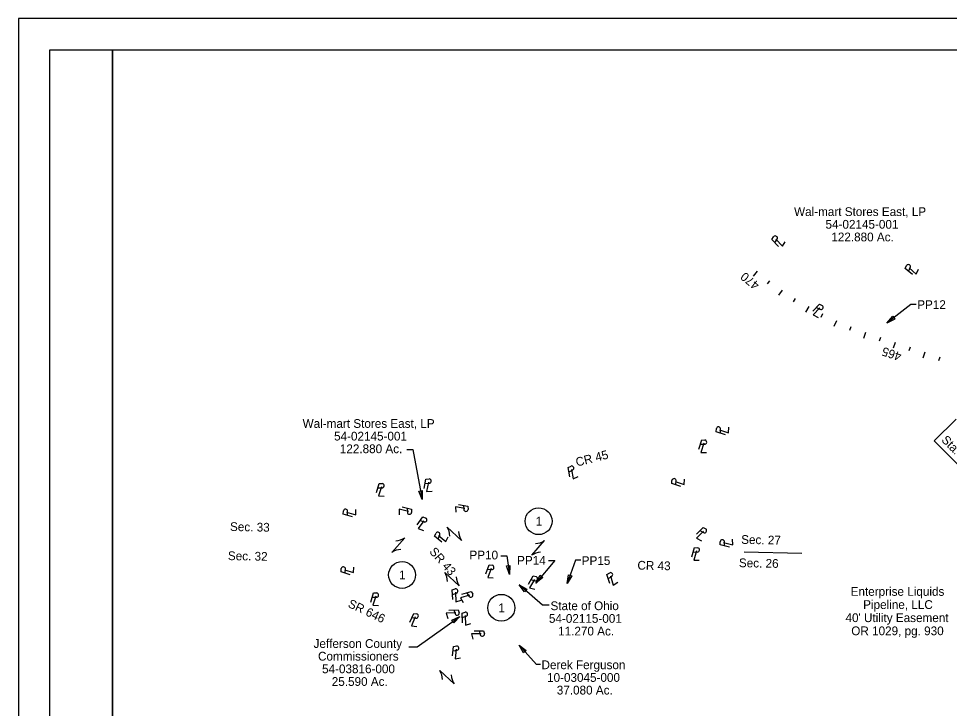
# Model space of a CAD drawing. Extents: x -98503 to 58976, y -493381 to 14884.
# Drawn here: x -26 to 2951, y 2199 to 4405 of the extents above; entities that cross this region are included whole.
import ezdxf

# ---------------------------------------------------------------- set-up
doc = ezdxf.new("R2010")
doc.units = 0
for name, color, linetype in [('DV_X_Property_Line', 7, 'Continuous'), ('DV_X_Section_VMS_Line', 7, 'Continuous'), ('RW_X_CL_100_Stations', 7, 'Continuous'), ('SH_Cut_Line', 7, 'Continuous'), ('SH_Data', 7, 'Continuous'), ('SH_Text', 7, 'Continuous')]:
    doc.layers.add(name, color=color, linetype=linetype)

msp = doc.modelspace()

# ---------------------------------------------------------------- linework, layer by layer
at = {"layer": 'DV_X_Property_Line'}
for p, q in [((2393.3, 3688.5), (2400.2, 3699.4)), ((2402.8, 3691.9), (2402.8, 3691.9)), ((2820.6, 3596.8), (2826.1, 3608.5)), ((2829.7, 3601.4), (2829.7, 3601.4)), ((2525.7, 3481.7), (2537.1, 3475.6)), ((2529.8, 3472.4), (2529.8, 3472.4)), ((2218.9, 3079.2), (2219.6, 3092.1)), ((2225.5, 3086.8), (2225.5, 3086.8)), ((2154.8, 3044.2), (2167.8, 3043.7)), ((2162.6, 3037.7), (2162.6, 3037.7)), ((1734.5, 2955.5), (1746.1, 2961.2)), ((1744.4, 2953.4), (1744.4, 2953.4)), ((1274.4, 2918.1), (1287.3, 2919)), ((2076.5, 2913.7), (2077.2, 2926.6)), ((2083.2, 2921.4), (2083.2, 2921.4)), ((1123.4, 2904.9), (1136.3, 2904.4)), ((1131.2, 2898.4), (1131.2, 2898.4)), ((1282.8, 2912.5), (1282.8, 2912.5)), ((1025.9, 2816.3), (1026.4, 2829.2)), ((1211, 2831.2), (1211, 2831.2)), ((1217.1, 2839.4), (1217.4, 2826.4)), ((1391.2, 2840), (1391.2, 2840)), ((1396.8, 2848.4), (1397.8, 2835.5)), ((1032.5, 2824), (1032.5, 2824)), ((1258.7, 2799.7), (1270.9, 2795.3)), ((1264.1, 2791.1), (1264.1, 2791.1)), ((1390.1, 2736.4), (1344.4, 2779)), ((1168, 2697.7), (1208.9, 2744.9)), ((1315.5, 2741.1), (1321, 2752.8)), ((1324.5, 2745.6), (1324.5, 2745.6)), ((1367.3, 2757.7), (1367.3, 2757.7)), ((2153.3, 2767.9), (2164.6, 2761.4)), ((2157.2, 2758.5), (2157.2, 2758.5)), ((1188.5, 2721.3), (1188.5, 2721.3)), ((1615.1, 2688.8), (1656, 2736)), ((1635.5, 2712.4), (1635.5, 2712.4)), ((2232.4, 2718.7), (2232, 2731.7)), ((2238.3, 2727), (2238.3, 2727)), ((2131.8, 2699.5), (2144.7, 2699.1)), ((2139.6, 2693.1), (2139.6, 2693.1)), ((1018.9, 2631.5), (1019.4, 2644.5)), ((1025.4, 2639.3), (1025.4, 2639.3)), ((1336.8, 2633.4), (1382.8, 2591.1)), ((1474.2, 2644.6), (1487.1, 2643.3)), ((1481.6, 2637.6), (1481.6, 2637.6)), ((1860.1, 2614), (1871.1, 2620.8)), ((1359.8, 2612.3), (1359.8, 2612.3)), ((1612.7, 2611), (1625.2, 2607.5)), ((1618.7, 2602.8), (1618.7, 2602.8)), ((1870.2, 2612.9), (1870.2, 2612.9)), ((1361.9, 2563.7), (1374.2, 2567.8)), ((1407.5, 2569), (1414.5, 2558)), ((1105.5, 2555), (1118.5, 2554.6)), ((1113.3, 2548.5), (1113.3, 2548.5)), ((1371.5, 2560.3), (1371.5, 2560.3)), ((1406.5, 2558.9), (1406.5, 2558.9)), ((1362.5, 2504.4), (1362.5, 2504.4)), ((1366, 2513.9), (1370, 2501.5)), ((1231.8, 2489.9), (1244.6, 2487.8)), ((1238.7, 2482.4), (1238.7, 2482.4)), ((1393.1, 2489.7), (1405.4, 2493.6)), ((1402.6, 2486.2), (1402.6, 2486.2)), ((1447, 2447.3), (1450.3, 2434.7)), ((1443.1, 2437.9), (1443.1, 2437.9)), ((1363.4, 2383.2), (1376.2, 2385.1)), ((1372.2, 2378.3), (1372.2, 2378.3)), ((1366.7, 2277.2), (1321, 2319.8)), ((1343.9, 2298.5), (1343.9, 2298.5))]:
    msp.add_line(p, q, dxfattribs=at)
for points in [[(2404.5, 3676.4), (2383.6, 3698.9), (2389.1, 3707.6)], [(2396.1, 3699.3), (2416.9, 3676.8), (2426.2, 3691.6)], [(2833.2, 3586.2), (2809.7, 3606), (2814.2, 3615.3)], [(2822.1, 3607.9), (2845.4, 3588.1), (2852.9, 3603.9)], [(2514.5, 3469.6), (2535.4, 3492.1), (2544.5, 3487.2)], [(2536.7, 3479.6), (2515.8, 3457.3), (2531.2, 3449)], [(2216.1, 3090), (2245.2, 3080.6), (2246.1, 3098)], [(2234.6, 3074.1), (2205.4, 3083.5), (2205.9, 3093.8)], [(2150, 3028.5), (2159, 3057.8), (2169.3, 3057.4)], [(2165.7, 3047.2), (2156.6, 3017.9), (2174, 3017.2)], [(1737.6, 2939.4), (1731.7, 2969.5), (1741, 2974)], [(1742.6, 2963.2), (1748.3, 2933.2), (1764.1, 2940.8)], [(1118.6, 2889.1), (1127.5, 2918.5), (1137.8, 2918.1)], [(1271.3, 2902), (1277, 2932.1), (1287.3, 2932.8)], [(1284.8, 2922.2), (1279, 2892.2), (1296.4, 2893.4)], [(2092.2, 2908.7), (2063, 2918.1), (2063.6, 2928.4)], [(2073.8, 2924.6), (2102.9, 2915.1), (2103.8, 2932.5)], [(1134.2, 2907.9), (1125.2, 2878.6), (1142.7, 2878)], [(1041.7, 2811.5), (1012.4, 2820.4), (1012.8, 2830.7)], [(1023, 2827.1), (1052.2, 2818), (1052.9, 2835.5)], [(1220.7, 2828.8), (1191, 2836), (1191.4, 2818.5)], [(1201.1, 2843.2), (1230.9, 2836.1), (1231.1, 2825.7)], [(1401, 2838), (1370.9, 2843.8), (1372.2, 2826.4)], [(1380.7, 2851.5), (1410.8, 2845.8), (1411.5, 2835.5)], [(1249.3, 2786.2), (1266.8, 2811.4), (1276.5, 2807.8)], [(1269.9, 2799.2), (1252.3, 2774.2), (1268.7, 2768.2)], [(2141.8, 2756.1), (2163.3, 2778), (2172.2, 2772.9)], [(1328, 2730.5), (1304.6, 2750.2), (1309.1, 2759.6)], [(1317, 2752.2), (1340.3, 2732.3), (1347.8, 2748.1)], [(2164.3, 2765.5), (2142.8, 2743.7), (2157.9, 2735.1)], [(2228.7, 2729.3), (2258.5, 2722.4), (2257.9, 2739.9)], [(2127.1, 2683.8), (2135.8, 2713.2), (2146.2, 2712.8)], [(2248.4, 2715.1), (2218.5, 2721.9), (2218.2, 2732.2)], [(2142.6, 2702.6), (2133.7, 2673.3), (2151.2, 2672.7)], [(1015.9, 2642.3), (1045.2, 2633.2), (1045.9, 2650.7)], [(1468.5, 2629.1), (1479.1, 2657.9), (1489.4, 2656.9)], [(1034.6, 2626.7), (1005.3, 2635.7), (1005.7, 2646)], [(1485.2, 2646.9), (1474.5, 2618.2), (1491.8, 2616.5)], [(1604.4, 2596.7), (1619.8, 2623.2), (1629.8, 2620.4)], [(1864.9, 2598.2), (1855.9, 2627.5), (1864.7, 2633)], [(1867.4, 2622.5), (1876.2, 2593.2), (1891.1, 2602.4)], [(1623.9, 2611.3), (1608.3, 2585), (1625.2, 2580.3)], [(1100.7, 2539.3), (1109.6, 2568.6), (1120, 2568.2)], [(1363, 2547.2), (1360.9, 2577.8), (1370.7, 2581.1)], [(1370.9, 2570.3), (1372.8, 2539.7), (1389.4, 2545.3)], [(1416.1, 2561.7), (1386.9, 2552.6), (1396.2, 2537.9)], [(1391.8, 2564), (1421.1, 2573.3), (1426.6, 2564.5)], [(1116.3, 2558), (1107.3, 2528.8), (1124.8, 2528.1)], [(1225.1, 2474.9), (1237.6, 2502.9), (1247.8, 2501.2)], [(1372.5, 2504.7), (1341.9, 2503.3), (1347.2, 2486.7)], [(1349.6, 2513.1), (1380.2, 2514.6), (1383.3, 2504.7)], [(1393.9, 2473.2), (1392.4, 2503.9), (1402.2, 2507)], [(1242.9, 2491.5), (1230.3, 2463.6), (1247.6, 2460.8)], [(1402.2, 2496.1), (1403.6, 2465.5), (1420.3, 2470.8)], [(1430.6, 2447.3), (1461.2, 2447.3), (1463.9, 2437.3)], [(1453, 2437.8), (1422.4, 2437.9), (1426.9, 2421)], [(1361.6, 2366.9), (1365, 2397.4), (1375.2, 2398.9)], [(1373.5, 2388.1), (1370, 2357.7), (1387.2, 2360.3)]]:
    msp.add_lwpolyline(points, dxfattribs=at)
for centre, radius, start, end in [((2394.3, 3703.1), 6.9, 328.1946, 139.0517), ((2819.9, 3611.4), 6.9, 335.0874, 145.9445), ((2540.3, 3481.7), 6.9, 242.2769, 53.134), ((2212.7, 3092.4), 6.9, 357.4879, 168.345), ((2168, 3050.6), 6.9, 268.2218, 79.0789), ((1743.1, 2967.4), 6.9, 296.276, 107.1331), ((1136.5, 2911.3), 6.9, 268.506, 79.3631), ((1286.8, 2925.9), 6.9, 274.5218, 85.3789), ((2070.3, 2927), 6.9, 357.3924, 168.2495), ((1019.5, 2829.4), 6.9, 358.324, 169.1812), ((1404.7, 2836.1), 6.9, 184.6321, 355.4892), ((1224.3, 2826.6), 6.9, 181.8507, 352.7078), ((1273.2, 2801.8), 6.9, 250.421, 61.2781), ((1299.8, 2749.9), 53.4, 0.4848, 33.1273), ((2168, 2767.5), 6.9, 240.7652, 51.6223), ((1178.2, 2788.5), 53.4, 272.5603, 305.2028), ((1314.8, 2755.7), 6.9, 335.0874, 145.9445), ((1434.8, 2765.6), 53.4, 180.4848, 213.1273), ((1625.2, 2779.6), 53.4, 272.5603, 305.2028), ((2144.9, 2706), 6.9, 268.7088, 79.5659), ((2225.1, 2731.4), 6.9, 2.4151, 173.2723), ((1198.8, 2654.1), 53.4, 92.5603, 125.2028), ((1645.8, 2645.2), 53.4, 92.5603, 125.2028), ((1012.5, 2644.7), 6.9, 358.1938, 169.0509), ((1487.7, 2650.2), 6.9, 264.9836, 75.8407), ((1292.3, 2604), 53.4, 0.8571, 33.4997), ((1627, 2614.2), 6.9, 254.9565, 65.8137), ((1867.4, 2626.6), 6.9, 302.3371, 113.1942), ((1427.3, 2620.6), 53.4, 180.8571, 213.4997), ((1118.7, 2561.5), 6.9, 268.3543, 79.2114), ((1371.9, 2574.3), 6.9, 289.0385, 99.8956), ((1420.3, 2561.8), 6.9, 212.8326, 23.6898), ((1245.7, 2494.6), 6.9, 261.1438, 72.0009), ((1376.5, 2503.7), 6.9, 198.0982, 8.9553), ((1403.3, 2500.2), 6.9, 288.0982, 98.9553), ((1457, 2436.6), 6.9, 195.2765, 6.1337), ((1375.2, 2392), 6.9, 278.8871, 89.7442), ((1276.3, 2290.7), 53.4, 0.4848, 33.1273), ((1411.4, 2306.4), 53.4, 180.4848, 213.1273)]:
    msp.add_arc(centre, radius, start, end, dxfattribs=at)
at = {"layer": 'DV_X_Section_VMS_Line'}
msp.add_line((2294.8, 2699.4), (2478.9, 2695.7), dxfattribs=at)
at = {"layer": 'RW_X_CL_100_Stations'}
for p, q in [((2336.5, 3596.9), (2323.9, 3581.4)), ((2375.8, 3566), (2368.6, 3556.4)), ((2416.4, 3536.9), (2405.1, 3520.4)), ((2458.3, 3509.5), (2451.9, 3499.3)), ((2501.3, 3484), (2491.4, 3466.6)), ((2545.3, 3460.4), (2539.9, 3449.7)), ((2590.4, 3438.7), (2582.1, 3420.5)), ((2636.4, 3419), (2631.9, 3407.9)), ((2683.1, 3401.4), (2676.5, 3382.5)), ((2730.5, 3385.4), (2726.7, 3374)), ((2777.9, 3369.6), (2771.6, 3350.6)), ((2825.4, 3353.8), (2821.6, 3342.4)), ((2872.8, 3338), (2866.5, 3319)), ((2920.2, 3322.2), (2916.4, 3310.8))]:
    msp.add_line(p, q, dxfattribs=at)
at = {"layer": 'SH_Cut_Line'}
msp.add_lwpolyline([(-26.1, 5), (6773.9, 5), (6773.9, 4405), (-26.1, 4405)], close=True, dxfattribs=at)
at = {"layer": 'SH_Data'}
for points in [[(73.9, 4305), (273.9, 4305), (273.9, 105), (73.9, 105)], [(273.9, 4305), (6673.9, 4305), (6673.9, 105), (273.9, 105)]]:
    msp.add_lwpolyline(points, close=True, dxfattribs=at)
at = {"layer": 'SH_Text'}
for p, q in [((2902.9, 3054.7), (2973.1, 3124.2)), ((2902.9, 3054.7), (3111, 2844.6)), ((1630.1, 2339.6), (1574.6, 2401.6)), ((1643.4, 2339.6), (1630.1, 2339.6))]:
    msp.add_line(p, q, dxfattribs=at)
for points in [[(2845.2, 3491), (2828.2, 3491), (2751.5, 3431.6)], [(1215.5, 3027.4), (1235.1, 3027.4), (1264.5, 2867.5)], [(1516.3, 2687.5), (1535.9, 2687.5), (1543.8, 2627.5)], [(1669.1, 2672.2), (1688.7, 2672.2), (1628.9, 2599.9)], [(1772.2, 2673.2), (1755.2, 2673.2), (1728.7, 2598.2)], [(1671.5, 2528.8), (1649.2, 2528.8), (1575.3, 2594.3)], [(1221.9, 2396.3), (1249.1, 2396.3), (1385.3, 2493)]]:
    msp.add_lwpolyline(points, dxfattribs=at)
for points in [[(2770.2, 3453.2), (2777.1, 3444.3), (2751.5, 3431.6)], [(1253.9, 2894), (1264.9, 2896), (1264.5, 2867.5)], [(1534.6, 2654.5), (1545.7, 2656), (1543.8, 2627.5)], [(1642.5, 2625.1), (1651.1, 2617.9), (1628.9, 2599.9)], [(1732.8, 2626.5), (1743.3, 2622.8), (1728.7, 2598.2)], [(1600, 2579.9), (1592.6, 2571.5), (1575.3, 2594.3)], [(1365.7, 2472.2), (1359.2, 2481.3), (1385.3, 2493)], [(1597.4, 2384.5), (1589.1, 2377), (1574.6, 2401.6)]]:
    msp.add_lwpolyline(points, close=True, dxfattribs=at)
for centre in [(1637.2, 2797.8), (1200.5, 2625.9), (1517.9, 2520.8)]:
    msp.add_circle(centre, 43, dxfattribs=at)

# ---------------------------------------------------------------- texts
at = {"layer": 'RW_X_CL_100_Stations'}
for s, rotation, p in [('470', 140.8439, (2346.1, 3556.9)), ('465', 161.5631, (2800.5, 3335.7))]:
    msp.add_text(s, height=28, rotation=rotation, dxfattribs=at).set_placement(p)
at = {"layer": 'SH_Text'}
for s, p in [('Wal-mart Stores East, LP', (2454.4, 3773.7)), ('54-02145-001', (2555.1, 3733.2)), ('122.880 Ac.', (2573.6, 3692.7)), ('PP12', (2848.4, 3476.4)), ('Wal-mart Stores East, LP', (882.3, 3096.3)), ('54-02145-001', (982.9, 3055.8)), ('122.880 Ac.', (1001.4, 3015.3)), ('1', (1627.8, 2783.8)), ('PP10', (1416, 2675.5)), ('PP14', (1568.4, 2658.5)), ('PP15', (1775.1, 2657.7)), ('1', (1191.1, 2611.9)), ('Enterprise Liquids', (2635.4, 2559.1)), ('1', (1508.5, 2506.8)), ('State of Ohio', (1675.3, 2513.3)), ('Pipeline, LLC', (2675.5, 2517.1)), ('54-02115-001', (1670.3, 2472.8)), ("40' Utility Easement", (2618.9, 2475.1)), ('11.270 Ac.', (1699.7, 2432.3)), ('OR 1029, pg. 930', (2637.4, 2433.1)), ('Jefferson County', (917.4, 2392.5)), ('Commissioners', (931.6, 2352)), ('Derek Ferguson', (1646.5, 2324.5)), ('54-03816-000', (944.5, 2311.5)), ('25.590 Ac.', (975.6, 2271)), ('10-03045-000', (1664.3, 2284)), ('37.080 Ac.', (1695.4, 2243.5))]:
    msp.add_text(s, height=28, dxfattribs=at).set_placement(p)
for s, rotation, p in [('Sta. 461+25.00', 314.7167, (2923.6, 3055.6)), ('CR 45', 14.3586, (1759.8, 2972.2)), ('Sec. 33', 358.8658, (649.9, 2766.6)), ('Sec. 27', 358.8658, (2285, 2725.4)), ('SR 43', 311.2481, (1285.9, 2699.3)), ('Sec. 32', 358.8658, (643.1, 2673.5)), ('CR 43', 358.8658, (1953.1, 2643)), ('Sec. 26', 358.8658, (2277.7, 2650.9)), ('SR 646', 334.64, (1024.9, 2524.5))]:
    msp.add_text(s, height=28, rotation=rotation, dxfattribs=at).set_placement(p)

doc.saveas('drawing.dxf')
